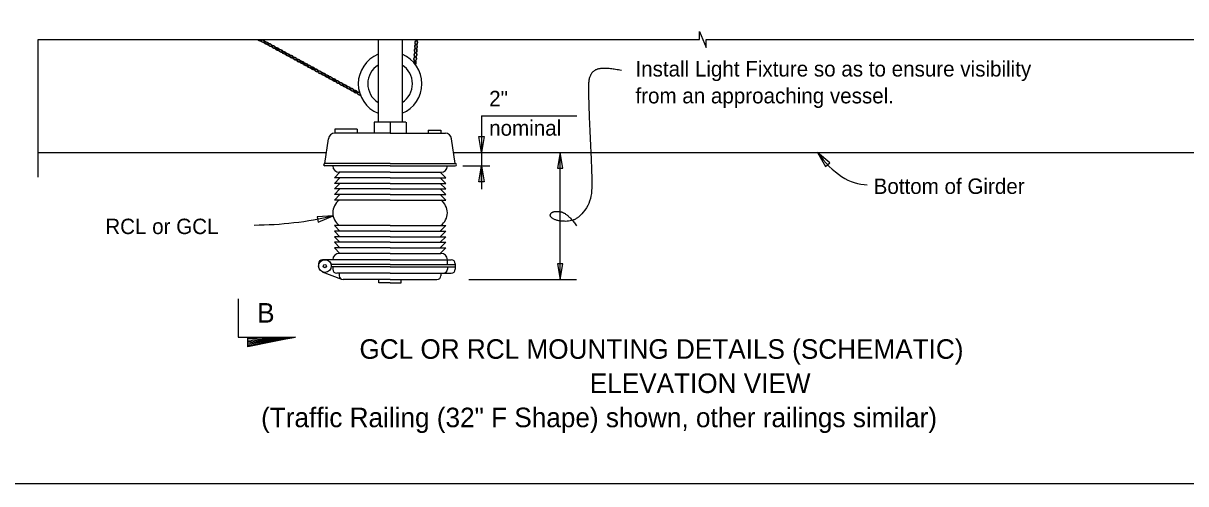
# Model space of a CAD drawing. Extents: x 83976.6 to 84012, y 72958.9 to 72975.6.
# Drawn here: x 83982.35 to 83989.96, y 72960.16 to 72963.17 of the extents above; entities that cross this region are included whole.
import ezdxf

# ---------------------------------------------------------------- set-up
doc = ezdxf.new("R2010")
doc.units = 0
for name, color, linetype in [('DSText', 7, 'Continuous'), ('DSTitle', 7, 'Continuous'), ('Patterning', 7, 'Continuous'), ('RefPtStaTie', 7, 'Continuous'), ('SheetLines_dp', 7, 'Continuous'), ('SupstrConc', 7, 'Continuous')]:
    doc.layers.add(name, color=color, linetype=linetype)

msp = doc.modelspace()

# ---------------------------------------------------------------- linework, layer by layer
at = {"layer": 'DSText'}
for p, q in [((83984.6697, 72963.068), (83984.6697, 72962.5269)), ((83984.828, 72963.068), (83984.828, 72962.5269)), ((83984.3869, 72962.48), (83984.3869, 72962.454)), ((83984.5327, 72962.48), (83984.3869, 72962.48)), ((83984.7488, 72962.454), (83984.3869, 72962.454)), ((83984.5327, 72962.48), (83984.5327, 72962.454)), ((83984.853, 72962.5269), (83984.6446, 72962.5269)), ((83984.6447, 72962.5268), (83984.6447, 72962.454)), ((83984.7488, 72962.454), (83985.1108, 72962.454)), ((83984.7489, 72962.5268), (83984.7489, 72962.454)), ((83984.8531, 72962.5268), (83984.8531, 72962.454)), ((83984.9988, 72962.4748), (83985.0821, 72962.4748)), ((83984.9988, 72962.4748), (83984.9988, 72962.454)), ((83985.0821, 72962.4748), (83985.0821, 72962.454)), ((83984.3216, 72962.2562), (83984.3456, 72962.4185)), ((83985.1759, 72962.2562), (83985.1519, 72962.4185)), ((83984.7488, 72962.2561), (83984.3216, 72962.2561)), ((83984.7488, 72962.2405), (83984.3216, 72962.2405)), ((83984.7488, 72962.2561), (83985.1759, 72962.2561)), ((83984.7488, 72962.2405), (83985.1759, 72962.2405)), ((83984.7488, 72962.1988), (83984.4155, 72962.1988)), ((83984.7488, 72962.1988), (83985.0821, 72962.1988)), ((83984.7488, 72961.6258), (83984.306, 72961.6258)), ((83984.7488, 72961.6675), (83984.4155, 72961.6675)), ((83984.7488, 72961.6675), (83985.0821, 72961.6675)), ((83984.7488, 72961.6258), (83985.1499, 72961.6258)), ((83985.1238, 72961.5946), (83985.1238, 72961.6258)), ((83984.28, 72961.5998), (83984.28, 72961.5842)), ((83984.4323, 72961.4973), (83984.3068, 72961.5453)), ((83984.7489, 72961.5945), (83984.3621, 72961.5945)), ((83984.7489, 72961.5789), (83984.3631, 72961.5789)), ((83984.3738, 72961.579), (83984.3738, 72961.5633)), ((83984.7489, 72961.5945), (83985.176, 72961.5945)), ((83984.7489, 72961.5789), (83985.176, 72961.5789)), ((83985.1238, 72961.579), (83985.1238, 72961.5633)), ((83985.1759, 72961.5998), (83985.1759, 72961.5633)), ((83984.7488, 72961.5373), (83984.3998, 72961.5373)), ((83984.4155, 72961.5373), (83984.4155, 72961.5216)), ((83984.7488, 72961.4956), (83984.4415, 72961.4956)), ((83984.676, 72961.4747), (83984.676, 72961.4955)), ((83984.7489, 72961.4747), (83984.676, 72961.4747)), ((83984.7488, 72961.5373), (83985.1499, 72961.5373)), ((83984.7488, 72961.4956), (83985.0561, 72961.4956)), ((83984.7489, 72961.4747), (83984.8218, 72961.4747)), ((83984.8218, 72961.4747), (83984.8218, 72961.4955)), ((83985.0821, 72961.5373), (83985.0821, 72961.5216))]:
    msp.add_line(p, q, dxfattribs=at)
for radius in [0.0416, 0.0104]:
    msp.add_circle((83984.3217, 72961.5842), radius, dxfattribs=at)
for centre, radius, start, end in [((83984.3868, 72962.4124), 0.0417, 90, 171.57567), ((83985.1106, 72962.4124), 0.0417, 8.42433, 90), ((83984.3216, 72962.2483), 0.00781, 90, 270), ((83984.4155, 72962.2405), 0.0417, 180, 270), ((83985.0821, 72962.2405), 0.0417, 270, 0), ((83985.1759, 72962.2483), 0.00781, 270, 90), ((83984.306, 72961.5998), 0.026, 90, 180), ((83984.4155, 72961.6258), 0.0417, 90, 180), ((83985.0821, 72961.6258), 0.0417, 0, 90), ((83985.1499, 72961.5998), 0.026, 0, 90), ((83984.3998, 72961.5633), 0.026, 180, 270), ((83985.0978, 72961.5633), 0.026, 270, 0), ((83985.1499, 72961.5633), 0.026, 270.00345, 0), ((83984.4415, 72961.5216), 0.026, 180, 270), ((83985.0561, 72961.5216), 0.026, 270, 0)]:
    msp.add_arc(centre, radius, start, end, dxfattribs=at)
at = {"layer": 'DSTitle'}
for p, q in [((83984.4206, 72962.1988), (83984.3842, 72962.1623)), ((83984.4206, 72962.1623), (83984.3842, 72962.1259)), ((83984.749, 72962.1622), (83984.3843, 72962.1622)), ((83984.7489, 72962.1622), (83985.1135, 72962.1622)), ((83985.0769, 72962.1988), (83985.1134, 72962.1623)), ((83985.0769, 72962.1623), (83985.1134, 72962.1259)), ((83984.4206, 72962.1259), (83984.3842, 72962.0894)), ((83984.4206, 72962.0894), (83984.3842, 72962.053)), ((83984.749, 72962.1258), (83984.3843, 72962.1258)), ((83984.749, 72962.0893), (83984.3843, 72962.0893)), ((83984.7489, 72962.1258), (83985.1135, 72962.1258)), ((83984.7489, 72962.0893), (83985.1135, 72962.0893)), ((83985.0769, 72962.1259), (83985.1134, 72962.0894)), ((83985.0769, 72962.0894), (83985.1134, 72962.053)), ((83984.4206, 72962.053), (83984.3842, 72962.0165)), ((83984.749, 72962.0529), (83984.3843, 72962.0529)), ((83984.749, 72962.0164), (83984.3843, 72962.0164)), ((83984.7489, 72962.0529), (83985.1135, 72962.0529)), ((83984.7489, 72962.0164), (83985.1135, 72962.0164)), ((83985.0769, 72962.053), (83985.1134, 72962.0165)), ((83984.4206, 72961.8134), (83984.3842, 72961.8498)), ((83984.749, 72961.8497), (83984.3843, 72961.8497)), ((83984.7489, 72961.8497), (83985.1135, 72961.8497)), ((83985.0769, 72961.8134), (83985.1134, 72961.8498)), ((83984.4206, 72961.7769), (83984.3842, 72961.8134)), ((83984.4206, 72961.7405), (83984.3842, 72961.7769)), ((83984.749, 72961.8133), (83984.3843, 72961.8133)), ((83984.749, 72961.7768), (83984.3843, 72961.7768)), ((83984.7489, 72961.8133), (83985.1135, 72961.8133)), ((83984.7489, 72961.7768), (83985.1135, 72961.7768)), ((83985.0769, 72961.7769), (83985.1134, 72961.8134)), ((83985.0769, 72961.7405), (83985.1134, 72961.7769)), ((83984.4206, 72961.704), (83984.3842, 72961.7405)), ((83984.4206, 72961.6675), (83984.3842, 72961.704)), ((83984.749, 72961.7404), (83984.3843, 72961.7404)), ((83984.749, 72961.7039), (83984.3843, 72961.7039)), ((83984.7489, 72961.7404), (83985.1135, 72961.7404)), ((83984.7489, 72961.7039), (83985.1135, 72961.7039)), ((83985.0769, 72961.704), (83985.1134, 72961.7405)), ((83985.0769, 72961.6675), (83985.1134, 72961.704))]:
    msp.add_line(p, q, dxfattribs=at)
for centre, radius, start, end in [((83984.7489, 72962.7781), 0.2084, 112.30644, 247.69356), ((83984.7489, 72962.7781), 0.2084, 292.32192, 67.67808), ((83984.7489, 72962.7781), 0.146, 122.80227, 237.19773), ((83984.7489, 72962.7781), 0.146, 302.82659, 57.17341), ((83984.4778, 72961.9332), 0.1041, 126.81262, 233.18738), ((83985.0197, 72961.9332), 0.1041, 306.81262, 53.18738)]:
    msp.add_arc(centre, radius, start, end, dxfattribs=at)
for centre, major_axis, ratio, start_param, end_param in [((83983.8928, 72963.0696), (-0.0135, 0.0073), 0.530594, 0.963145, 3.776778), ((83983.8928, 72963.0696), (-0.0117, 0.0064), 0.458548, 1.074165, 3.810831), ((83984.9218, 72963.0744), (0.001, 0.0153), 0.530594, 2.038886, 4.311456), ((83984.9218, 72963.0744), (0.0008, 0.0133), 0.458548, 2.106923, 4.234305), ((83984.9118, 72962.9153), (0.001, 0.0153), 0.530594, 3.785956, 7.749185), ((83984.9118, 72962.9153), (0.0008, 0.0133), 0.458548, 3.769896, 7.882867), ((83984.5459, 72962.7135), (-0.0135, 0.0073), 0.530594, 4.817186, 8.780415), ((83984.5459, 72962.7135), (-0.0117, 0.0064), 0.458548, 4.683503, 8.796475)]:
    msp.add_ellipse(centre, major_axis=major_axis, ratio=ratio, start_param=start_param, end_param=end_param, dxfattribs=at)
for centre, major_axis, ratio in [((83983.9161, 72963.0569), (-0.0135, 0.0073), 0.530594), ((83983.9161, 72963.0569), (-0.0117, 0.0064), 0.458548), ((83984.9202, 72963.0479), (0.001, 0.0153), 0.530594), ((83983.9395, 72963.0442), (-0.0135, 0.0073), 0.530594), ((83983.9395, 72963.0442), (-0.0117, 0.0064), 0.458548), ((83983.9628, 72963.0315), (-0.0135, 0.0073), 0.530594), ((83983.9628, 72963.0315), (-0.0117, 0.0064), 0.458548), ((83983.9861, 72963.0188), (-0.0135, 0.0073), 0.530594), ((83983.9861, 72963.0188), (-0.0117, 0.0064), 0.458548), ((83984.0094, 72963.006), (-0.0135, 0.0073), 0.530594), ((83984.0094, 72963.006), (-0.0117, 0.0064), 0.458548), ((83984.0327, 72962.9933), (-0.0135, 0.0073), 0.530594), ((83984.0327, 72962.9933), (-0.0117, 0.0064), 0.458548), ((83984.0561, 72962.9806), (-0.0135, 0.0073), 0.530594), ((83984.0561, 72962.9806), (-0.0117, 0.0064), 0.458548), ((83984.9168, 72962.9949), (0.001, 0.0153), 0.530594), ((83984.9185, 72963.0214), (0.001, 0.0153), 0.530594), ((83984.9168, 72962.9949), (0.0008, 0.0133), 0.458548), ((83984.9185, 72963.0214), (0.0008, 0.0133), 0.458548), ((83984.9202, 72963.0479), (0.0008, 0.0133), 0.458548), ((83984.0794, 72962.9679), (-0.0135, 0.0073), 0.530594), ((83984.0794, 72962.9679), (-0.0117, 0.0064), 0.458548), ((83984.1027, 72962.9552), (-0.0135, 0.0073), 0.530594), ((83984.1027, 72962.9552), (-0.0117, 0.0064), 0.458548), ((83984.126, 72962.9424), (-0.0135, 0.0073), 0.530594), ((83984.126, 72962.9424), (-0.0117, 0.0064), 0.458548), ((83984.1494, 72962.9297), (-0.0135, 0.0073), 0.530594), ((83984.1494, 72962.9297), (-0.0117, 0.0064), 0.458548), ((83984.1727, 72962.917), (-0.0135, 0.0073), 0.530594), ((83984.1727, 72962.917), (-0.0117, 0.0064), 0.458548), ((83984.196, 72962.9043), (-0.0135, 0.0073), 0.530594), ((83984.196, 72962.9043), (-0.0117, 0.0064), 0.458548), ((83984.9134, 72962.9418), (0.001, 0.0153), 0.530594), ((83984.9151, 72962.9684), (0.001, 0.0153), 0.530594), ((83984.9134, 72962.9418), (0.0008, 0.0133), 0.458548), ((83984.9151, 72962.9684), (0.0008, 0.0133), 0.458548), ((83984.2193, 72962.8916), (-0.0135, 0.0073), 0.530594), ((83984.2193, 72962.8916), (-0.0117, 0.0064), 0.458548), ((83984.2427, 72962.8788), (-0.0135, 0.0073), 0.530594), ((83984.2427, 72962.8788), (-0.0117, 0.0064), 0.458548), ((83984.266, 72962.8661), (-0.0135, 0.0073), 0.530594), ((83984.266, 72962.8661), (-0.0117, 0.0064), 0.458548), ((83984.2893, 72962.8534), (-0.0135, 0.0073), 0.530594), ((83984.2893, 72962.8534), (-0.0117, 0.0064), 0.458548), ((83984.3126, 72962.8407), (-0.0135, 0.0073), 0.530594), ((83984.3126, 72962.8407), (-0.0117, 0.0064), 0.458548), ((83984.3359, 72962.8279), (-0.0135, 0.0073), 0.530594), ((83984.3359, 72962.8279), (-0.0117, 0.0064), 0.458548), ((83984.3593, 72962.8152), (-0.0135, 0.0073), 0.530594), ((83984.3593, 72962.8152), (-0.0117, 0.0064), 0.458548), ((83984.3826, 72962.8025), (-0.0135, 0.0073), 0.530594), ((83984.3826, 72962.8025), (-0.0117, 0.0064), 0.458548), ((83984.4059, 72962.7898), (-0.0135, 0.0073), 0.530594), ((83984.4059, 72962.7898), (-0.0117, 0.0064), 0.458548), ((83984.4292, 72962.7771), (-0.0135, 0.0073), 0.530594), ((83984.4292, 72962.7771), (-0.0117, 0.0064), 0.458548), ((83984.4526, 72962.7643), (-0.0135, 0.0073), 0.530594), ((83984.4526, 72962.7643), (-0.0117, 0.0064), 0.458548), ((83984.4759, 72962.7516), (-0.0135, 0.0073), 0.530594), ((83984.4759, 72962.7516), (-0.0117, 0.0064), 0.458548), ((83984.4992, 72962.7389), (-0.0135, 0.0073), 0.530594), ((83984.4992, 72962.7389), (-0.0117, 0.0064), 0.458548), ((83984.5225, 72962.7262), (-0.0135, 0.0073), 0.530594), ((83984.5225, 72962.7262), (-0.0117, 0.0064), 0.458548)]:
    msp.add_ellipse(centre, major_axis=major_axis, ratio=ratio, dxfattribs=at)
at = {"layer": 'RefPtStaTie'}
msp.add_lwpolyline([(83976.5859, 72973.1323), (83997.1112, 72973.1323), (83997.1112, 72960.1592), (83976.5859, 72960.1592)], close=True, dxfattribs=at)
at = {"layer": 'SheetLines_dp'}
for p, q in [((83985.3473, 72962.5688), (83985.3473, 72962.3289)), ((83985.3473, 72962.5688), (83985.9729, 72962.5688)), ((83985.2155, 72962.3289), (83985.4733, 72962.3289)), ((83985.3473, 72962.3289), (83985.3473, 72962.089)), ((83985.862, 72961.4956), (83985.862, 72962.3289)), ((83985.2263, 72962.2405), (83985.403, 72962.2405)), ((83985.3473, 72962.1397), (83985.3473, 72962.2405)), ((83985.2642, 72961.4956), (83985.969, 72961.4956)), ((83984.1294, 72961.1189), (83983.816, 72961.0705)), ((83984.1294, 72961.1189), (83983.816, 72961.108)), ((83984.1294, 72961.1189), (83983.8169, 72961.098)), ((83983.8177, 72961.0639), (83984.1294, 72961.1189)), ((83984.1294, 72961.1189), (83983.8177, 72961.0797)), ((83984.1294, 72961.1189), (83983.8177, 72961.0889))]:
    msp.add_line(p, q, dxfattribs=at)
for points in [[(83982.4439, 72963.068), (83986.7743, 72963.068), (83986.7743, 72963.1196), (83986.7968, 72963.068), (83986.8193, 72963.0163), (83986.8193, 72963.068), (83990.5105, 72963.068)], [(83982.4439, 72962.1667), (83982.4439, 72963.068)], [(83983.7544, 72961.3697), (83983.7544, 72961.1189), (83984.1294, 72961.1189), (83983.8169, 72961.0564), (83983.8169, 72961.1189)]]:
    msp.add_lwpolyline(points, dxfattribs=at)
for points in [[(83985.3649, 72962.433), (83985.3473, 72962.3289), (83985.3296, 72962.433)], [(83985.8621, 72962.3289), (83985.8444, 72962.2247), (83985.8797, 72962.2247)], [(83987.5484, 72962.3289), (83987.6007, 72962.2371), (83987.628, 72962.2595)], [(83985.3296, 72962.1364), (83985.3473, 72962.2405), (83985.3649, 72962.1364)], [(83984.3757, 72961.9133), (83984.2703, 72961.9069), (83984.2782, 72961.8726)], [(83985.8621, 72961.4956), (83985.8797, 72961.5997), (83985.8444, 72961.5997)]]:
    msp.add_lwpolyline(points, close=True, dxfattribs=at)
msp.add_arc((83983.8496, 72964.1819), 2.3288, 270.23541, 283.05474, dxfattribs=at)
msp.add_ellipse((83987.8915, 72963.9534), major_axis=(-0.0171, -1.8368), ratio=0.385201, start_param=5.801208, end_param=6.283151, dxfattribs=at)
msp.add_open_spline([(83986.264, 72962.8648), (83986.1502, 72962.8887), (83986.0549, 72962.8544), (83986.0448, 72962.7235), (83986.0702, 72962.2059), (83986.0702, 72962.0056), (83985.9661, 72961.8773), (83985.8434, 72961.8773), (83985.7885, 72961.9112), (83985.8176, 72961.9483), (83985.9112, 72961.9322), (83985.9694, 72961.8482)], degree=2, dxfattribs=at)
at = {"layer": 'SupstrConc'}
for p, q in [((83982.4439, 72962.3289), (83984.3323, 72962.3289)), ((83985.1651, 72962.3289), (83990.5104, 72962.3289))]:
    msp.add_line(p, q, dxfattribs=at)

# ---------------------------------------------------------------- texts
at = {"layer": 'Patterning'}
for s, height, p in [('Bottom of Girder', 0.1008, (83987.9159, 72962.0569)), ('RCL or GCL', 0.1008, (83982.8836, 72961.7939)), ('B', 0.128, (83983.8781, 72961.2143))]:
    msp.add_text(s, height=height, dxfattribs=at).set_placement(p)
at = {"layer": 'SheetLines_dp'}
for s, height, p in [('Install Light Fixture so as to ensure visibility ', 0.1008, (83986.3558, 72962.8256)), ('2"', 0.1008, (83985.3977, 72962.631)), ('from an approaching vessel.', 0.1008, (83986.3558, 72962.6496)), ('nominal', 0.1008, (83985.3977, 72962.438)), ('GCL OR RCL MOUNTING DETAILS (SCHEMATIC)', 0.128, (83984.5482, 72960.9773)), ('ELEVATION VIEW', 0.128, (83986.0567, 72960.7533)), ('(Traffic Railing (32" F Shape) shown, other railings similar)', 0.128, (83983.904, 72960.5293))]:
    msp.add_text(s, height=height, dxfattribs=at).set_placement(p)

doc.saveas('drawing.dxf')
